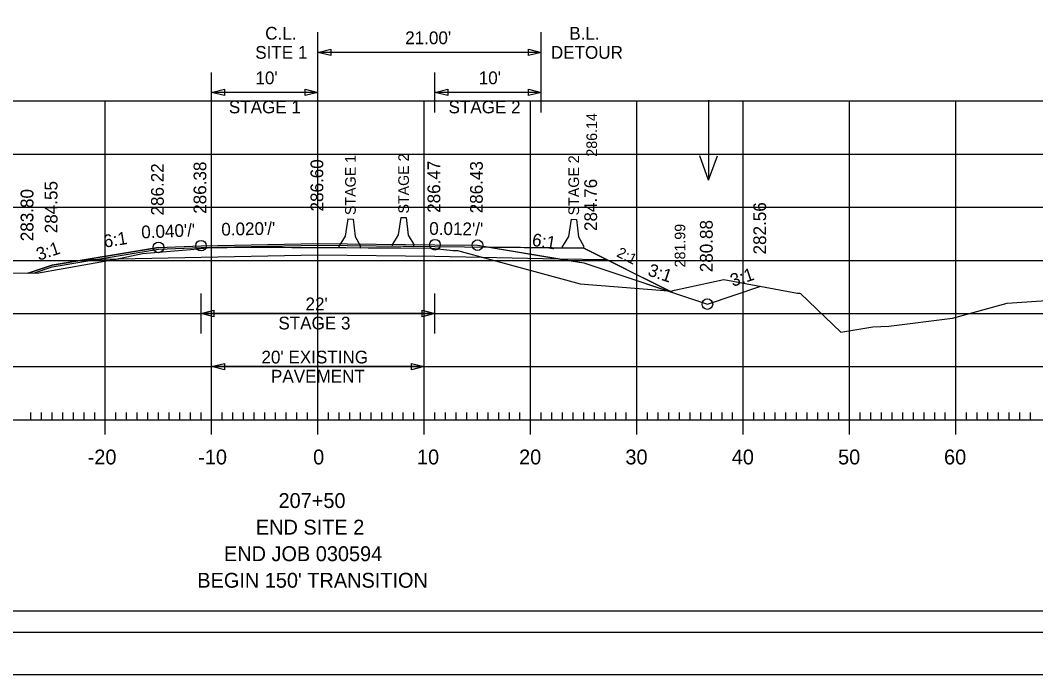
# Model space of a CAD drawing. Extents: x 1368713 to 1370673, y 380279 to 380950.
# Drawn here: x 1370481.6 to 1370577.1, y 380737.1 to 380798.7 of the extents above; entities that cross this region are included whole.
import ezdxf

# ---------------------------------------------------------------- set-up
doc = ezdxf.new("R2010")
doc.units = 0
for name, color, linetype in [('R_Alt Surface', 7, 'Continuous'), ('R_Axis', 7, 'Continuous'), ('R_Axis Annot', 7, 'Continuous'), ('R_Border', 7, 'Continuous'), ('R_CONC BARRIER', 7, 'Continuous'), ('R_Exist Surface', 7, 'Continuous'), ('R_Fin Surface', 7, 'Continuous'), ('R_Grid', 7, 'Continuous'), ('R_No Plot', 7, 'Continuous'), ('R_ROW Annot', 7, 'Continuous'), ('R_Stage 3 EW', 7, 'Continuous'), ('R_Water Annot', 7, 'Continuous'), ('R_Xsect Elev', 7, 'Continuous'), ('R_Xsect Slope', 7, 'Continuous')]:
    doc.layers.add(name, color=color, linetype=linetype)

msp = doc.modelspace()

# ---------------------------------------------------------------- linework, layer by layer
at = {"layer": 'R_Alt Surface'}
msp.add_line((1370532.244, 380776.248), (1370536.783, 380776.157), dxfattribs=at)
for points in [[(1370482.86, 380774.889), (1370484.629, 380775.478), (1370487.788, 380776.005), (1370494.629, 380777.145), (1370498.629, 380777.305), (1370509.629, 380777.525), (1370520.629, 380777.397), (1370534.629, 380777.234), (1370537.13, 380775.984), (1370542.931, 380773.083)], [(1370494.629, 380777.312), (1370484.629, 380775.645)], [(1370524.629, 380777.517), (1370534.629, 380775.851)], [(1370487.788, 380776.172), (1370498.629, 380776.388), (1370509.629, 380776.608), (1370520.629, 380776.481), (1370532.244, 380776.248)], [(1370484.629, 380775.645), (1370482.369, 380774.892)], [(1370534.629, 380775.851), (1370546.253, 380771.976)], [(1370482.369, 380774.892), (1370482.369, 380774.892), (1370482.357, 380774.896)], [(1370546.253, 380771.976), (1370546.253, 380771.976), (1370551.274, 380773.65)]]:
    msp.add_lwpolyline(points, dxfattribs=at)
at = {"layer": 'R_Axis'}
for p, q in [((1370482.629, 380761.092), (1370482.629, 380761.792)), ((1370483.629, 380761.092), (1370483.629, 380761.792)), ((1370484.629, 380761.092), (1370484.629, 380761.792)), ((1370485.629, 380761.092), (1370485.629, 380761.792)), ((1370486.629, 380761.092), (1370486.629, 380761.792)), ((1370487.629, 380761.092), (1370487.629, 380761.792)), ((1370488.629, 380761.092), (1370488.629, 380761.792)), ((1370489.629, 380759.692), (1370489.629, 380762.492)), ((1370490.629, 380761.092), (1370490.629, 380761.792)), ((1370491.629, 380761.092), (1370491.629, 380761.792)), ((1370492.629, 380761.092), (1370492.629, 380761.792)), ((1370493.629, 380761.092), (1370493.629, 380761.792)), ((1370494.629, 380761.092), (1370494.629, 380761.792)), ((1370495.629, 380761.092), (1370495.629, 380761.792)), ((1370496.629, 380761.092), (1370496.629, 380761.792)), ((1370497.629, 380761.092), (1370497.629, 380761.792)), ((1370498.629, 380761.092), (1370498.629, 380761.792)), ((1370499.629, 380759.692), (1370499.629, 380762.492)), ((1370500.629, 380761.092), (1370500.629, 380761.792)), ((1370501.629, 380761.092), (1370501.629, 380761.792)), ((1370502.629, 380761.092), (1370502.629, 380761.792)), ((1370503.629, 380761.092), (1370503.629, 380761.792)), ((1370504.629, 380761.092), (1370504.629, 380761.792)), ((1370505.629, 380761.092), (1370505.629, 380761.792)), ((1370506.629, 380761.092), (1370506.629, 380761.792)), ((1370507.629, 380761.092), (1370507.629, 380761.792)), ((1370508.629, 380761.092), (1370508.629, 380761.792)), ((1370509.629, 380759.692), (1370509.629, 380762.492)), ((1370510.629, 380761.092), (1370510.629, 380761.792)), ((1370511.629, 380761.092), (1370511.629, 380761.792)), ((1370512.629, 380761.092), (1370512.629, 380761.792)), ((1370513.629, 380761.092), (1370513.629, 380761.792)), ((1370514.629, 380761.092), (1370514.629, 380761.792)), ((1370515.629, 380761.092), (1370515.629, 380761.792)), ((1370516.629, 380761.092), (1370516.629, 380761.792)), ((1370517.629, 380761.092), (1370517.629, 380761.792)), ((1370518.629, 380761.092), (1370518.629, 380761.792)), ((1370519.629, 380759.692), (1370519.629, 380762.492)), ((1370520.629, 380761.092), (1370520.629, 380761.792)), ((1370521.629, 380761.092), (1370521.629, 380761.792)), ((1370522.629, 380761.092), (1370522.629, 380761.792)), ((1370523.629, 380761.092), (1370523.629, 380761.792)), ((1370524.629, 380761.092), (1370524.629, 380761.792)), ((1370525.629, 380761.092), (1370525.629, 380761.792)), ((1370526.629, 380761.092), (1370526.629, 380761.792)), ((1370527.629, 380761.092), (1370527.629, 380761.792)), ((1370528.629, 380761.092), (1370528.629, 380761.792)), ((1370529.629, 380759.692), (1370529.629, 380762.492)), ((1370530.629, 380761.092), (1370530.629, 380761.792)), ((1370531.629, 380761.092), (1370531.629, 380761.792)), ((1370532.629, 380761.092), (1370532.629, 380761.792)), ((1370533.629, 380761.092), (1370533.629, 380761.792)), ((1370534.629, 380761.092), (1370534.629, 380761.792)), ((1370535.629, 380761.092), (1370535.629, 380761.792)), ((1370536.629, 380761.092), (1370536.629, 380761.792)), ((1370537.629, 380761.092), (1370537.629, 380761.792)), ((1370538.629, 380761.092), (1370538.629, 380761.792)), ((1370539.629, 380759.692), (1370539.629, 380762.492)), ((1370540.629, 380761.092), (1370540.629, 380761.792)), ((1370541.629, 380761.092), (1370541.629, 380761.792)), ((1370542.629, 380761.092), (1370542.629, 380761.792)), ((1370543.629, 380761.092), (1370543.629, 380761.792)), ((1370544.629, 380761.092), (1370544.629, 380761.792)), ((1370545.629, 380761.092), (1370545.629, 380761.792)), ((1370546.629, 380761.092), (1370546.629, 380761.792)), ((1370547.629, 380761.092), (1370547.629, 380761.792)), ((1370548.629, 380761.092), (1370548.629, 380761.792)), ((1370549.629, 380759.692), (1370549.629, 380762.492)), ((1370550.629, 380761.092), (1370550.629, 380761.792)), ((1370551.629, 380761.092), (1370551.629, 380761.792)), ((1370552.629, 380761.092), (1370552.629, 380761.792)), ((1370553.629, 380761.092), (1370553.629, 380761.792)), ((1370554.629, 380761.092), (1370554.629, 380761.792)), ((1370555.629, 380761.092), (1370555.629, 380761.792)), ((1370556.629, 380761.092), (1370556.629, 380761.792)), ((1370557.629, 380761.092), (1370557.629, 380761.792)), ((1370558.629, 380761.092), (1370558.629, 380761.792)), ((1370559.629, 380759.692), (1370559.629, 380762.492)), ((1370560.629, 380761.092), (1370560.629, 380761.792)), ((1370561.629, 380761.092), (1370561.629, 380761.792)), ((1370562.629, 380761.092), (1370562.629, 380761.792)), ((1370563.629, 380761.092), (1370563.629, 380761.792)), ((1370564.629, 380761.092), (1370564.629, 380761.792)), ((1370565.629, 380761.092), (1370565.629, 380761.792)), ((1370566.629, 380761.092), (1370566.629, 380761.792)), ((1370567.629, 380761.092), (1370567.629, 380761.792)), ((1370568.629, 380761.092), (1370568.629, 380761.792)), ((1370569.629, 380759.692), (1370569.629, 380762.492)), ((1370570.629, 380761.092), (1370570.629, 380761.792)), ((1370571.629, 380761.092), (1370571.629, 380761.792)), ((1370572.629, 380761.092), (1370572.629, 380761.792)), ((1370573.629, 380761.092), (1370573.629, 380761.792)), ((1370574.629, 380761.092), (1370574.629, 380761.792)), ((1370575.629, 380761.092), (1370575.629, 380761.792)), ((1370576.629, 380761.092), (1370576.629, 380761.792)), ((1370369.629, 380761.092), (1370649.629, 380761.092))]:
    msp.add_line(p, q, dxfattribs=at)
at = {"layer": 'R_Border'}
msp.add_line((1370667.809, 380741.092), (1370351.629, 380741.092), dxfattribs=at)
at = {"layer": 'R_CONC BARRIER'}
for p, q in [((1370512.433, 380779.99), (1370512.933, 380779.98)), ((1370517.433, 380780.128), (1370517.933, 380780.118)), ((1370533.433, 380779.959), (1370533.933, 380779.949)), ((1370511.629, 380777.305), (1370511.632, 380777.472)), ((1370511.629, 380777.305), (1370513.629, 380777.265)), ((1370513.629, 380777.265), (1370513.632, 380777.432)), ((1370516.629, 380777.444), (1370516.633, 380777.61)), ((1370516.629, 380777.444), (1370518.629, 380777.404)), ((1370518.629, 380777.404), (1370518.632, 380777.57)), ((1370532.629, 380777.274), (1370532.633, 380777.441)), ((1370532.629, 380777.274), (1370534.629, 380777.234)), ((1370534.629, 380777.234), (1370534.632, 380777.401))]:
    msp.add_line(p, q, dxfattribs=at)
for points in [[(1370512.433, 380779.99), (1370512.181, 380778.352), (1370511.632, 380777.472)], [(1370512.933, 380779.98), (1370513.119, 380778.333), (1370513.632, 380777.432)], [(1370517.433, 380780.128), (1370517.182, 380778.49), (1370516.633, 380777.61)], [(1370517.933, 380780.118), (1370518.119, 380778.471), (1370518.632, 380777.57)], [(1370533.433, 380779.959), (1370533.182, 380778.321), (1370532.633, 380777.441)], [(1370533.933, 380779.949), (1370534.119, 380778.302), (1370534.632, 380777.401)]]:
    msp.add_lwpolyline(points, dxfattribs=at)
at = {"layer": 'R_Exist Surface'}
msp.add_lwpolyline([(1370480.001, 380774.929), (1370483.18, 380774.884), (1370490.614, 380776.218), (1370493.132, 380776.736), (1370497.652, 380777.119), (1370499.506, 380777.316), (1370501.083, 380777.315), (1370504.185, 380777.342), (1370506.258, 380777.321), (1370507.185, 380777.312), (1370509.259, 380777.294), (1370510.185, 380777.296), (1370512.261, 380777.309), (1370514.339, 380777.277), (1370517.409, 380777.254), (1370520.306, 380777.243), (1370522.33, 380777.034), (1370522.752, 380777.012), (1370533.597, 380774.085), (1370534.283, 380773.87), (1370542.606, 380773.233), (1370542.719, 380773.194), (1370542.814, 380773.19), (1370543.144, 380773.285), (1370547.787, 380774.287), (1370554.741, 380773.016), (1370554.932, 380772.997), (1370554.998, 380772.958), (1370558.8, 380769.348), (1370561.827, 380769.846), (1370563.328, 380769.89), (1370569.311, 380770.66), (1370574.453, 380772.072), (1370586.383, 380772.892)], dxfattribs=at)
at = {"layer": 'R_Fin Surface'}
for points in [[(1370482.357, 380774.896), (1370482.369, 380774.892), (1370484.629, 380775.645), (1370487.788, 380776.172), (1370494.629, 380777.312), (1370498.629, 380777.472), (1370509.629, 380777.692), (1370520.629, 380777.564), (1370524.629, 380777.517), (1370532.244, 380776.248), (1370534.629, 380775.851), (1370546.253, 380771.976), (1370551.274, 380773.65)], [(1370494.629, 380777.312), (1370498.629, 380777.472), (1370509.629, 380777.692), (1370520.629, 380777.564), (1370524.629, 380777.517)]]:
    msp.add_lwpolyline(points, dxfattribs=at)
at = {"layer": 'R_Grid'}
for p, q in [((1370369.629, 380791.092), (1370649.629, 380791.092)), ((1370489.629, 380761.092), (1370489.629, 380791.092)), ((1370499.629, 380761.092), (1370499.629, 380791.092)), ((1370509.629, 380761.092), (1370509.629, 380791.092)), ((1370519.629, 380761.092), (1370519.629, 380791.092)), ((1370529.629, 380761.092), (1370529.629, 380791.092)), ((1370539.629, 380761.092), (1370539.629, 380791.092)), ((1370549.629, 380761.092), (1370549.629, 380791.092)), ((1370559.629, 380761.092), (1370559.629, 380791.092)), ((1370569.629, 380761.092), (1370569.629, 380791.092)), ((1370369.629, 380786.092), (1370649.629, 380786.092)), ((1370369.629, 380781.092), (1370649.629, 380781.092)), ((1370369.629, 380776.092), (1370649.629, 380776.092)), ((1370369.629, 380771.092), (1370649.629, 380771.092)), ((1370369.629, 380766.092), (1370649.629, 380766.092)), ((1370369.629, 380761.092), (1370649.629, 380761.092))]:
    msp.add_line(p, q, dxfattribs=at)
at = {"layer": 'R_No Plot'}
for points in [[(1370339.221, 380950.446), (1370672.561, 380950.446), (1370672.561, 380737.109), (1370339.221, 380737.109)], [(1370353.629, 380944.552), (1370603.169, 380944.552), (1370603.169, 380934.672), (1370620.709, 380934.672), (1370644.809, 380934.672), (1370644.809, 380912.339), (1370665.809, 380912.339), (1370665.809, 380743.092), (1370353.629, 380743.092)], [(1370353.629, 380841.822), (1370665.809, 380841.822), (1370665.809, 380743.092), (1370353.629, 380743.092)]]:
    msp.add_lwpolyline(points, close=True, dxfattribs=at)
for centre in [(1370498.629, 380777.472), (1370498.629, 380777.472), (1370520.629, 380777.564), (1370520.629, 380777.564), (1370524.629, 380777.517), (1370524.629, 380777.517), (1370494.629, 380777.312), (1370494.629, 380777.312), (1370546.253, 380771.976), (1370546.253, 380771.976)]:
    msp.add_circle(centre, 0.5, dxfattribs=at)
at = {"layer": 'R_ROW Annot'}
for p, q in [((1370509.629, 380793.777), (1370509.629, 380797.545)), ((1370530.629, 380793.777), (1370530.629, 380797.545)), ((1370530.629, 380795.661), (1370509.629, 380795.661)), ((1370499.629, 380790.008), (1370499.629, 380793.777)), ((1370509.629, 380790.008), (1370509.629, 380793.777)), ((1370520.629, 380790.008), (1370520.629, 380793.777)), ((1370530.629, 380790.008), (1370530.629, 380793.777)), ((1370509.629, 380791.893), (1370499.629, 380791.893)), ((1370530.629, 380791.893), (1370520.629, 380791.893)), ((1370498.629, 380769.207), (1370498.629, 380772.976)), ((1370520.629, 380769.207), (1370520.629, 380772.976)), ((1370520.629, 380771.092), (1370498.629, 380771.092)), ((1370499.629, 380764.207), (1370499.629, 380767.976)), ((1370519.629, 380764.207), (1370519.629, 380767.976)), ((1370519.629, 380766.092), (1370499.629, 380766.092))]:
    msp.add_line(p, q, dxfattribs=at)
for points in [[(1370510.829, 380795.361), (1370509.629, 380795.661), (1370510.829, 380795.961)], [(1370529.429, 380795.961), (1370530.629, 380795.661), (1370529.429, 380795.361)], [(1370500.829, 380791.593), (1370499.629, 380791.893), (1370500.829, 380792.193)], [(1370508.429, 380792.193), (1370509.629, 380791.893), (1370508.429, 380791.593)], [(1370521.829, 380791.593), (1370520.629, 380791.893), (1370521.829, 380792.193)], [(1370529.429, 380792.193), (1370530.629, 380791.893), (1370529.429, 380791.593)], [(1370499.829, 380770.792), (1370498.629, 380771.092), (1370499.829, 380771.392)], [(1370519.429, 380771.392), (1370520.629, 380771.092), (1370519.429, 380770.792)], [(1370500.829, 380765.792), (1370499.629, 380766.092), (1370500.829, 380766.392)], [(1370518.429, 380766.392), (1370519.629, 380766.092), (1370518.429, 380765.792)]]:
    msp.add_lwpolyline(points, close=True, dxfattribs=at)
at = {"layer": 'R_Stage 3 EW'}
for p, q in [((1370534.629, 380777.234), (1370525.704, 380777.338)), ((1370525.704, 380777.338), (1370532.244, 380776.248)), ((1370532.244, 380776.248), (1370534.629, 380775.851))]:
    msp.add_line(p, q, dxfattribs=at)
for points in [[(1370542.931, 380773.083), (1370542.717, 380773.19), (1370542.689, 380773.204), (1370534.629, 380777.234)], [(1370534.629, 380775.851), (1370542.447, 380773.245), (1370542.931, 380773.083)]]:
    msp.add_lwpolyline(points, dxfattribs=at)
at = {"layer": 'R_Water Annot'}
for p, q in [((1370546.372, 380791.172), (1370546.372, 380783.631)), ((1370546.372, 380783.631), (1370545.532, 380785.939)), ((1370546.372, 380783.631), (1370547.212, 380785.939))]:
    msp.add_line(p, q, dxfattribs=at)

# ---------------------------------------------------------------- texts
at = {"layer": 'R_Axis Annot'}
for s, p in [('-20', (1370487.97, 380756.892)), ('-10', (1370498.367, 380756.892)), ('0', (1370509.172, 380756.892)), ('10', (1370518.94, 380756.892)), ('20', (1370528.543, 380756.892)), ('30', (1370538.543, 380756.892)), ('40', (1370548.543, 380756.892)), ('50', (1370558.543, 380756.892)), ('60', (1370568.51, 380756.892)), ('207+50', (1370505.92, 380752.792)), ('END SITE 2', (1370503.786, 380750.292)), ('END JOB 030594', (1370500.788, 380747.792)), ("BEGIN 150' TRANSITION", (1370498.28, 380745.292))]:
    msp.add_text(s, height=1.4, dxfattribs=at).set_placement(p)
at = {"layer": 'R_CONC BARRIER'}
for s, p in [(' STAGE 1', (1370513.183, 380779.985)), (' STAGE 2', (1370518.183, 380780.123)), (' STAGE 2', (1370534.183, 380779.954))]:
    msp.add_text(s, height=1, rotation=90, dxfattribs=at).set_placement(p)
at = {"layer": 'R_ROW Annot'}
for s, p in [('C.L.', (1370504.665, 380796.857)), ('B.L.', (1370533.265, 380796.857)), ("21.00'", (1370517.833, 380796.431)), ('SITE 1', (1370503.73, 380795.057)), ('DETOUR', (1370531.531, 380795.057)), ("10'", (1370503.75, 380792.662)), ("10'", (1370524.75, 380792.662)), ('STAGE 1', (1370501.246, 380789.923)), ('STAGE 2', (1370521.906, 380789.923)), ("22'", (1370508.457, 380771.392)), ('STAGE 3', (1370505.906, 380769.592)), ("20' EXISTING", (1370504.314, 380766.392)), ('PAVEMENT', (1370505.212, 380764.592))]:
    msp.add_text(s, height=1.2, dxfattribs=at).set_placement(p)
at = {"layer": 'R_Xsect Elev'}
for s, height, p in [('286.14', 1, (1370535.876, 380785.849)), ('286.60', 1.2, (1370510.129, 380780.692)), ('286.22', 1.2, (1370495.129, 380780.312)), ('286.38', 1.2, (1370499.129, 380780.472)), ('286.47', 1.2, (1370521.129, 380780.564)), ('286.43', 1.2, (1370525.129, 380780.517)), ('284.76', 1.2, (1370535.876, 380778.851)), ('283.80', 1.2, (1370482.857, 380777.896)), ('283.80', 1.2, (1370482.869, 380777.892)), ('284.55', 1.2, (1370485.129, 380778.645)), ('284.55', 1.2, (1370485.129, 380778.645)), ('282.56', 1.2, (1370551.774, 380776.65)), ('280.88', 1.2, (1370546.753, 380774.976)), ('281.99', 1, (1370544.178, 380775.432))]:
    msp.add_text(s, height=height, rotation=90, dxfattribs=at).set_placement(p)
at = {"layer": 'R_Xsect Slope'}
for s, height, rotation, p in [("0.040'/'", 1.2, 2.29061, (1370493.034, 380778.149)), ("0.020'/'", 1.2, 1.14576, (1370500.549, 380778.41)), ("0.012'/'", 1.2, 359.33409, (1370520.086, 380778.495)), ('6:1', 1.2, 9.46234, (1370489.563, 380777.273)), ('6:1', 1.2, 350.53766, (1370529.695, 380777.479)), ('3:1', 1.2, 18.43493, (1370483.372, 380776.048)), ('2:1', 1, 333.43495, (1370537.639, 380776.494)), ('3:1', 1.2, 341.56507, (1370540.568, 380774.693)), ('3:1', 1.2, 18.43493, (1370548.637, 380773.592))]:
    msp.add_text(s, height=height, rotation=rotation, dxfattribs=at).set_placement(p)

doc.saveas('drawing.dxf')
